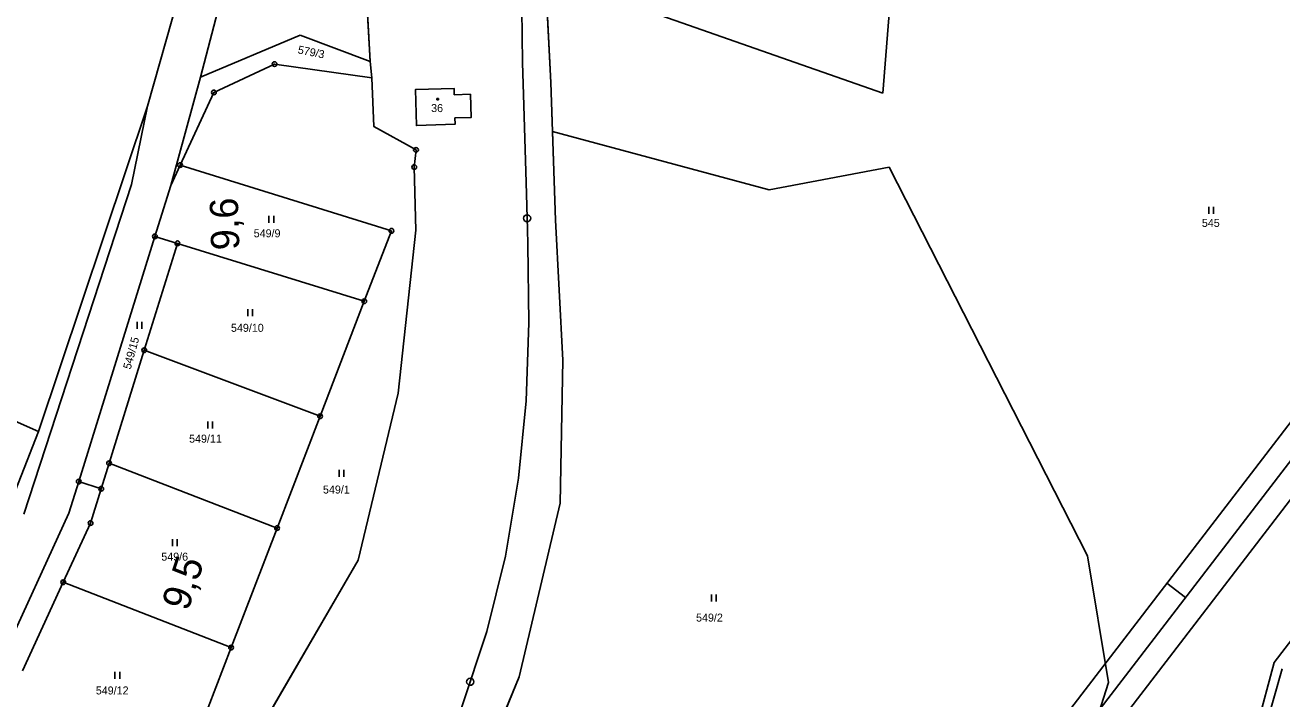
# Model space of a CAD drawing. Extents: x -866656 to -858817, y -1041816 to -1038653.
# Drawn here: x -862617.9 to -862351, y -1039602.1 to -1039458.9 of the extents above; entities that cross this region are included whole.
import ezdxf

# ---------------------------------------------------------------- set-up
doc = ezdxf.new("R2010")
doc.units = 0
for name, color, linetype in [('SZDC', 7, 'Continuous'), ('tisk ramy', 7, 'Continuous'), ('Vrstva 1', 7, 'Continuous'), ('Vrstva 53', 7, 'Continuous'), ('Vrstva 7', 7, 'Continuous')]:
    doc.layers.add(name, color=color, linetype=linetype)

msp = doc.modelspace()

# ---------------------------------------------------------------- linework, layer by layer
at = {"layer": 'SZDC'}
for points in [[(-862507.54, -1039446.34), (-862506.21, -1039471.12), (-862505.87, -1039481.53), (-862505.25, -1039500.36), (-862503.67, -1039530.11), (-862504.26, -1039560.51), (-862512.94, -1039597.44), (-862522.21, -1039619.87), (-862533.82, -1039639.47), (-862574.41, -1039691.56), (-862593.02, -1039711.09), (-862614.27, -1039728.82), (-862615.17, -1039729.57), (-862621.94, -1039738.72)], [(-862618.74, -1039701.53), (-862617.34, -1039679.93), (-862597.59, -1039662.79), (-862567.2, -1039636.61), (-862572.98, -1039634.36), (-862581.31, -1039629.28), (-862567.95, -1039608.49), (-862547.19, -1039572.66), (-862538.66, -1039537.19), (-862534.9, -1039502.5), (-862535.25, -1039489.12), (-862534.88, -1039485.46), (-862543.81, -1039480.51), (-862544.26, -1039470.12), (-862544.59, -1039466.71), (-862545.46, -1039451.11)]]:
    msp.add_lwpolyline(points, dxfattribs=at)
for points in [[(-862526.76, -1039473.74), (-862526.8, -1039472.4), (-862535.02, -1039472.66), (-862534.78, -1039480.28), (-862526.57, -1039480), (-862526.61, -1039478.68), (-862523.15, -1039478.56), (-862523.31, -1039473.63)], [(-862526.76, -1039473.74), (-862523.31, -1039473.63), (-862523.15, -1039478.56), (-862526.61, -1039478.68), (-862526.57, -1039480), (-862534.78, -1039480.28), (-862535.02, -1039472.66), (-862526.8, -1039472.4)]]:
    msp.add_lwpolyline(points, close=True, dxfattribs=at)
at = {"layer": 'tisk ramy'}
msp.add_line((-862375.41, -1039577.56), (-862371.45, -1039580.61), dxfattribs=at)
for points in [[(-862750.99, -1040083.46), (-861983.98, -1039083.83), (-862219.6, -1038903.04), (-862986.61, -1039902.67)], [(-862979.6, -1039901.75), (-862218.68, -1038910.05), (-861990.99, -1039084.75), (-862751.92, -1040076.45)], [(-862752.84, -1040069.45), (-862122.79, -1039248.31), (-862342.55, -1039079.69), (-862972.6, -1039900.83)], [(-862972.6, -1039900.83), (-862342.55, -1039079.69), (-862122.79, -1039248.31), (-862752.84, -1040069.45)]]:
    msp.add_lwpolyline(points, close=True, dxfattribs=at)
at = {"layer": 'Vrstva 1'}
for p, q in [((-862560.11, -1039390.55), (-862580.63, -1039469.99)), ((-862578.71, -1039429.27), (-862591.89, -1039476.19)), ((-862506.21, -1039471.12), (-862507.77, -1039442.09)), ((-862433.62, -1039446.66), (-862435.7, -1039473.43)), ((-862545.46, -1039451.11), (-862544.59, -1039466.71)), ((-862435.7, -1039473.43), (-862499.88, -1039450.91)), ((-862559.49, -1039461.08), (-862580.63, -1039469.99)), ((-862544.59, -1039466.71), (-862559.49, -1039461.08)), ((-862577.81, -1039473.25), (-862564.93, -1039467.23)), ((-862564.93, -1039467.23), (-862544.26, -1039470.12)), ((-862544.26, -1039470.12), (-862544.59, -1039466.71)), ((-862586.99, -1039493.02), (-862580.63, -1039469.99)), ((-862544.26, -1039470.12), (-862543.81, -1039480.51)), ((-862526.8, -1039472.4), (-862535.02, -1039472.66)), ((-862535.02, -1039472.66), (-862534.78, -1039480.28)), ((-862526.76, -1039473.74), (-862526.8, -1039472.4)), ((-862505.25, -1039500.36), (-862506.21, -1039471.12)), ((-862584.98, -1039488.69), (-862577.81, -1039473.25)), ((-862530.42, -1039474.55), (-862530.12, -1039474.55)), ((-862530.42, -1039474.85), (-862530.42, -1039474.55)), ((-862530.12, -1039474.85), (-862530.42, -1039474.85)), ((-862530.12, -1039474.55), (-862530.12, -1039474.85)), ((-862523.31, -1039473.63), (-862526.76, -1039473.74)), ((-862523.15, -1039478.56), (-862523.31, -1039473.63)), ((-862591.89, -1039476.19), (-862615.1, -1039545.3)), ((-862591.89, -1039476.19), (-862595.3, -1039492.82)), ((-862511.5, -1039492.41), (-862512.01, -1039476)), ((-862543.81, -1039480.51), (-862534.88, -1039485.46)), ((-862534.78, -1039480.28), (-862526.57, -1039480)), ((-862526.61, -1039478.68), (-862523.15, -1039478.56)), ((-862526.57, -1039480), (-862526.61, -1039478.68)), ((-862505.87, -1039481.53), (-862459.86, -1039493.97)), ((-862534.88, -1039485.46), (-862535.25, -1039489.12)), ((-862584.98, -1039488.69), (-862586.99, -1039493.02)), ((-862584.98, -1039488.69), (-862540.11, -1039502.66)), ((-862535.25, -1039489.12), (-862534.9, -1039502.5)), ((-862459.86, -1039493.97), (-862434.35, -1039489.16)), ((-862434.35, -1039489.16), (-862392.26, -1039571.69)), ((-862595.3, -1039492.82), (-862618.16, -1039562.84)), ((-862586.99, -1039493.02), (-862590.35, -1039503.83)), ((-862566.11, -1039500.94), (-862566.11, -1039499.44)), ((-862565.11, -1039499.44), (-862565.11, -1039500.94)), ((-862366.49, -1039499.06), (-862366.49, -1039497.56)), ((-862365.49, -1039497.56), (-862365.49, -1039499.06)), ((-862534.9, -1039502.5), (-862538.66, -1039537.19)), ((-862503.67, -1039530.11), (-862505.25, -1039500.36)), ((-862590.35, -1039503.83), (-862606.52, -1039555.94)), ((-862585.55, -1039505.32), (-862590.35, -1039503.83)), ((-862540.11, -1039502.66), (-862545.86, -1039517.62)), ((-862592.6, -1039528.02), (-862585.55, -1039505.32)), ((-862545.86, -1039517.62), (-862585.55, -1039505.32)), ((-862545.86, -1039517.62), (-862555.26, -1039542.07)), ((-862570.62, -1039520.79), (-862570.62, -1039519.29)), ((-862569.62, -1039519.29), (-862569.62, -1039520.79)), ((-862594.1, -1039523.49), (-862594.1, -1039521.99)), ((-862593.1, -1039521.99), (-862593.1, -1039523.49)), ((-862658.62, -1039526.31), (-862615.1, -1039545.3)), ((-862592.6, -1039528.02), (-862600.07, -1039552.06)), ((-862555.26, -1039542.07), (-862592.6, -1039528.02)), ((-862504.26, -1039560.51), (-862503.67, -1039530.11)), ((-862538.66, -1039537.19), (-862547.19, -1039572.66)), ((-862555.26, -1039542.07), (-862564.39, -1039565.82)), ((-862579.12, -1039544.66), (-862579.12, -1039543.16)), ((-862578.12, -1039543.16), (-862578.12, -1039544.66)), ((-862615.1, -1039545.3), (-862623.1, -1039565.76)), ((-862601.75, -1039557.47), (-862600.07, -1039552.06)), ((-862600.07, -1039552.06), (-862564.39, -1039565.82)), ((-862551.19, -1039554.93), (-862551.19, -1039553.43)), ((-862550.19, -1039553.43), (-862550.19, -1039554.93)), ((-862606.52, -1039555.94), (-862608.6, -1039562.63)), ((-862606.52, -1039555.94), (-862601.75, -1039557.47)), ((-862604.01, -1039564.76), (-862601.75, -1039557.47)), ((-862512.94, -1039597.44), (-862504.26, -1039560.51)), ((-862608.6, -1039562.63), (-862623, -1039594.08)), ((-862609.81, -1039577.35), (-862604.01, -1039564.76)), ((-862564.39, -1039565.82), (-862574.15, -1039591.21)), ((-862586.62, -1039569.66), (-862586.62, -1039568.16)), ((-862585.62, -1039568.16), (-862585.62, -1039569.66)), ((-862392.26, -1039571.69), (-862387.82, -1039598.64)), ((-862547.19, -1039572.66), (-862567.95, -1039608.49)), ((-862338.65, -1039576.09), (-862352.57, -1039594.36)), ((-862609.81, -1039577.35), (-862618.47, -1039596.14)), ((-862574.15, -1039591.21), (-862609.81, -1039577.35)), ((-862472.09, -1039581.42), (-862472.09, -1039579.92)), ((-862471.09, -1039579.92), (-862471.09, -1039581.42)), ((-862574.15, -1039591.21), (-862588.08, -1039627.45)), ((-862352.57, -1039594.36), (-862356.2, -1039607.88)), ((-862354.93, -1039610.02), (-862350.91, -1039595.75)), ((-862598.82, -1039597.87), (-862598.82, -1039596.37)), ((-862597.82, -1039596.37), (-862597.82, -1039597.87)), ((-862522.21, -1039619.87), (-862512.94, -1039597.44)), ((-862387.82, -1039598.64), (-862397.87, -1039630.18))]:
    msp.add_line(p, q, dxfattribs=at)
for points in [[(-862512.01, -1039476), (-862512.24, -1039466.87), (-862512.45, -1039449.84), (-862512.08, -1039433.48), (-862510.82, -1039417.56), (-862508.37, -1039401.8), (-862504.9, -1039386.68), (-862500.23, -1039371.45), (-862494.61, -1039356.98), (-862487.83, -1039342.57), (-862479.6, -1039328.11), (-862470.61, -1039314.75), (-862460.78, -1039302.18), (-862456.07, -1039296.77), (-862449.22, -1039289.53), (-862437.48, -1039278.49), (-862424.62, -1039268.05), (-862410.54, -1039258.33), (-862394.98, -1039249.32), (-862379.54, -1039241.95), (-862364.62, -1039236.19), (-862348.59, -1039231.34)], [(-862635.33, -1039727.96), (-862628.97, -1039724.2), (-862616.24, -1039716.36), (-862603.07, -1039707.37), (-862590.53, -1039697.47), (-862579.03, -1039687), (-862568.05, -1039675.52), (-862557.58, -1039662.82), (-862548.5, -1039650.05), (-862539.56, -1039635.32), (-862531.65, -1039619.63), (-862525.21, -1039604.06), (-862519.84, -1039587.79), (-862515.9, -1039571.79), (-862513.1, -1039555.19), (-862511.49, -1039538.76), (-862510.91, -1039522.22), (-862511.11, -1039505.52), (-862511.19, -1039502.39), (-862511.5, -1039492.41)]]:
    msp.add_lwpolyline(points, dxfattribs=at)
for centre, radius in [((-862564.93, -1039467.23), 0.5), ((-862564.93, -1039467.23), 0.01), ((-862577.81, -1039473.25), 0.5), ((-862577.81, -1039473.25), 0.01), ((-862534.88, -1039485.46), 0.5), ((-862534.88, -1039485.46), 0.01), ((-862584.98, -1039488.69), 0.5), ((-862584.98, -1039488.69), 0.01), ((-862535.25, -1039489.12), 0.5), ((-862535.25, -1039489.12), 0.01), ((-862540.11, -1039502.66), 0.5), ((-862590.35, -1039503.83), 0.5), ((-862590.35, -1039503.83), 0.01), ((-862585.55, -1039505.32), 0.5), ((-862540.11, -1039502.66), 0.01), ((-862585.55, -1039505.32), 0.01), ((-862545.86, -1039517.62), 0.5), ((-862545.86, -1039517.62), 0.01), ((-862592.6, -1039528.02), 0.5), ((-862592.6, -1039528.02), 0.01), ((-862555.26, -1039542.07), 0.5), ((-862555.26, -1039542.07), 0.01), ((-862600.07, -1039552.06), 0.5), ((-862600.07, -1039552.06), 0.01), ((-862606.52, -1039555.94), 0.5), ((-862606.52, -1039555.94), 0.01), ((-862601.75, -1039557.47), 0.5), ((-862601.75, -1039557.47), 0.01), ((-862604.01, -1039564.76), 0.5), ((-862604.01, -1039564.76), 0.01), ((-862564.39, -1039565.82), 0.5), ((-862564.39, -1039565.82), 0.01), ((-862609.81, -1039577.35), 0.5), ((-862609.81, -1039577.35), 0.01), ((-862574.15, -1039591.21), 0.5), ((-862574.15, -1039591.21), 0.01)]:
    msp.add_circle(centre, radius, dxfattribs=at)
at = {"layer": 'Vrstva 53'}
for points in [[(-862507.54, -1039446.34), (-862506.21, -1039471.12), (-862505.87, -1039481.53), (-862505.25, -1039500.36), (-862503.67, -1039530.11), (-862504.26, -1039560.51), (-862512.94, -1039597.44), (-862522.21, -1039619.87), (-862533.82, -1039639.47), (-862574.41, -1039691.56), (-862593.02, -1039711.09), (-862614.27, -1039728.82), (-862615.17, -1039729.57), (-862621.94, -1039738.72)], [(-862618.74, -1039701.53), (-862617.34, -1039679.93), (-862597.59, -1039662.79), (-862567.2, -1039636.61), (-862572.98, -1039634.36), (-862581.31, -1039629.28), (-862567.95, -1039608.49), (-862547.19, -1039572.66), (-862538.66, -1039537.19), (-862534.9, -1039502.5), (-862535.25, -1039489.12), (-862534.88, -1039485.46), (-862543.81, -1039480.51), (-862544.26, -1039470.12), (-862544.59, -1039466.71), (-862545.46, -1039451.11)]]:
    msp.add_lwpolyline(points, dxfattribs=at)
at = {"layer": 'Vrstva 7'}
for centre in [(-862511.27, -1039499.99), (-862523.37, -1039598.49)]:
    msp.add_circle(centre, 0.75, dxfattribs=at)

# ---------------------------------------------------------------- texts
at = {"layer": 'Vrstva 1'}
for s, rotation, p in [('579/3', 348.7305, (-862560.09, -1039464.94)), ('549/15', 74.6095, (-862595.5, -1039532.21))]:
    msp.add_text(s, height=1.7, rotation=rotation, dxfattribs=at).set_placement(p)
for s, p in [('36', (-862531.67, -1039477.42)), ('549/9', (-862569.35, -1039504.03)), ('545', (-862367.95, -1039501.83)), ('549/10', (-862574.18, -1039524.12)), ('549/11', (-862583.08, -1039547.68)), ('549/1', (-862554.64, -1039558.49)), ('549/6', (-862588.98, -1039572.75)), ('549/2', (-862475.39, -1039585.7)), ('549/12', (-862602.89, -1039601.18))]:
    msp.add_text(s, height=1.7, dxfattribs=at).set_placement(p)
at = {"layer": 'Vrstva 7'}
for s, rotation, p in [('9,6', 91.8069, (-862572.38, -1039506.68)), ('9,5', 71.7512, (-862583.33, -1039583.67))]:
    msp.add_text(s, height=6, rotation=rotation, dxfattribs=at).set_placement(p)

doc.saveas('drawing.dxf')
